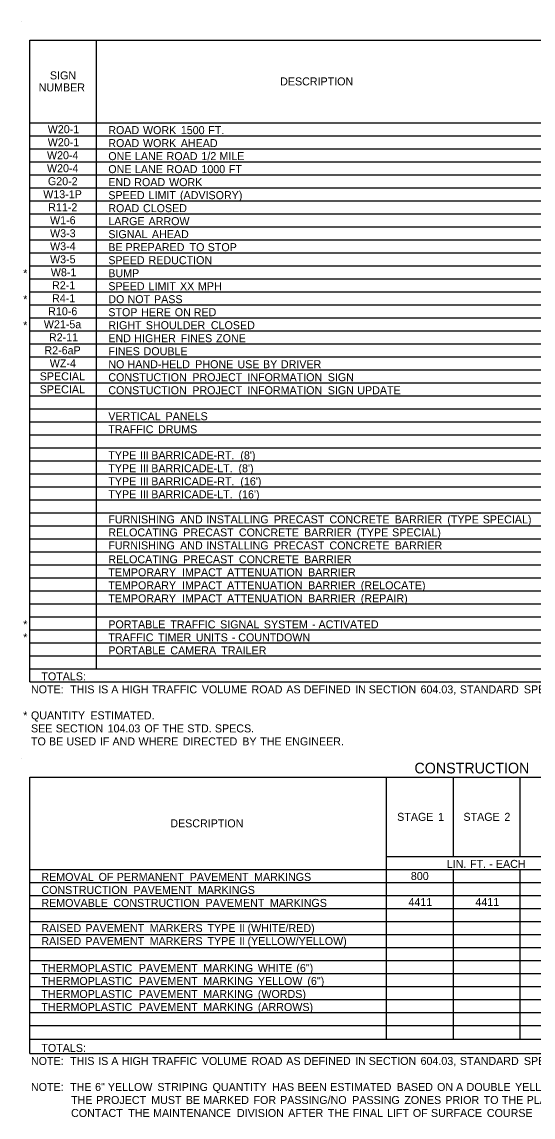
# Model space of a CAD drawing. Extents: x 107 to 7866, y 32 to 1473.
# Drawn here: x 107 to 490, y 67 to 888 of the extents above; entities that cross this region are included whole.
import ezdxf

# ---------------------------------------------------------------- set-up
doc = ezdxf.new("R2010")
doc.units = 0
doc.layers.add('Default', color=7, linetype='Continuous')

msp = doc.modelspace()

# ---------------------------------------------------------------- linework, layer by layer
at = {"layer": 'Default'}
for p, q in [((106.96, 888.35), (106.96, 888.35)), ((112.81, 874.7), (1625.52, 874.7)), ((112.81, 393.54), (112.81, 874.7)), ((112.81, 393.54), (112.81, 874.7)), ((163.02, 403.29), (163.02, 874.7)), ((112.81, 812.79), (1625.52, 812.79)), ((163.02, 500.79), (163.02, 812.79)), ((112.81, 803.04), (1625.52, 803.04)), ((112.81, 793.29), (1625.52, 793.29)), ((112.81, 783.54), (1625.52, 783.54)), ((112.81, 773.79), (1625.52, 773.79)), ((112.81, 764.04), (1625.52, 764.04)), ((112.81, 754.29), (1625.52, 754.29)), ((112.81, 744.54), (1625.52, 744.54)), ((112.81, 734.79), (1625.52, 734.79)), ((112.81, 725.04), (1625.52, 725.04)), ((112.81, 715.29), (1625.52, 715.29)), ((112.81, 705.54), (1625.52, 705.54)), ((112.81, 695.79), (1625.52, 695.79)), ((112.81, 686.04), (1625.52, 686.04)), ((112.81, 676.29), (1625.52, 676.29)), ((112.81, 666.54), (1625.52, 666.54)), ((112.81, 656.79), (1625.52, 656.79)), ((112.81, 647.04), (1625.52, 647.04)), ((112.81, 637.29), (1625.52, 637.29)), ((112.81, 627.54), (1625.52, 627.54)), ((112.81, 617.79), (1625.52, 617.79)), ((112.81, 608.04), (1625.52, 608.04)), ((112.81, 598.29), (1625.52, 598.29)), ((112.81, 588.54), (1625.52, 588.54)), ((112.81, 578.79), (1625.52, 578.79)), ((112.81, 569.04), (1625.52, 569.04)), ((112.81, 559.29), (1625.52, 559.29)), ((112.81, 549.54), (1625.52, 549.54)), ((112.81, 539.79), (1625.52, 539.79)), ((112.81, 530.04), (1625.52, 530.04)), ((112.81, 520.29), (1625.52, 520.29)), ((112.81, 510.54), (1625.52, 510.54)), ((112.81, 500.79), (163.02, 500.79)), ((112.81, 500.79), (1625.52, 500.79)), ((112.81, 491.04), (163.02, 491.04)), ((112.81, 491.04), (1625.52, 491.04)), ((163.02, 422.79), (163.02, 491.04)), ((112.81, 481.29), (1625.52, 481.29)), ((112.81, 471.54), (1625.52, 471.54)), ((112.81, 461.79), (1625.52, 461.79)), ((112.81, 452.04), (1625.52, 452.04)), ((112.81, 442.29), (1625.52, 442.29)), ((112.81, 432.54), (1625.52, 432.54)), ((112.81, 422.79), (1625.52, 422.79)), ((112.81, 413.04), (1625.52, 413.04)), ((163.02, 413.04), (495.01, 413.04)), ((163.02, 403.29), (163.02, 413.04)), ((112.81, 403.29), (1625.52, 403.29)), ((112.81, 393.54), (1625.52, 393.54)), ((106.96, 335.83), (106.96, 335.83)), ((112.81, 322.18), (1136.56, 322.18)), ((112.81, 114.99), (112.81, 322.18)), ((112.81, 114.99), (112.81, 322.18)), ((380.45, 125.71), (380.45, 322.18)), ((430.66, 262.7), (430.66, 322.18)), ((480.87, 262.7), (480.87, 322.18)), ((380.45, 262.7), (1136.56, 262.7)), ((112.81, 252.95), (1136.56, 252.95)), ((380.45, 125.71), (380.45, 252.95)), ((430.66, 125.71), (430.66, 252.95)), ((430.66, 125.71), (430.66, 252.95)), ((480.87, 125.71), (480.87, 252.95)), ((480.87, 125.71), (480.87, 252.95)), ((112.81, 243.2), (1136.56, 243.2)), ((112.81, 233.45), (1136.56, 233.45)), ((112.81, 223.7), (1136.56, 223.7)), ((112.81, 213.95), (1136.56, 213.95)), ((112.81, 204.2), (1136.56, 204.2)), ((112.81, 194.45), (1136.56, 194.45)), ((112.81, 184.7), (1136.56, 184.7)), ((112.81, 174.95), (1136.56, 174.95)), ((112.81, 165.2), (1136.56, 165.2)), ((112.81, 155.45), (1136.56, 155.45)), ((112.81, 145.7), (1136.56, 145.7)), ((112.81, 135.95), (1136.56, 135.95)), ((112.81, 125.71), (1136.56, 125.71)), ((112.81, 114.99), (1136.56, 114.99))]:
    msp.add_line(p, q, dxfattribs=at)

# ---------------------------------------------------------------- texts
for s, height, p in [('SIGN', 6, (128, 845.25)), ('DESCRIPTION', 6, (300.7, 840.75)), ('NUMBER', 6, (119.54, 836.25)), ('W20-1', 6, (126.34, 804.92)), ('ROAD', 6, (171.8, 804.24)), (' WORK', 6, (195.57, 804.24)), (' 1500', 6, (223.96, 804.24)), (' FT.', 6, (244.53, 804.24)), ('W20-1', 6, (126.34, 795.17)), ('ROAD', 6, (171.8, 794.49)), (' WORK', 6, (195.57, 794.49)), (' AHEAD', 6, (223.96, 794.49)), ('W20-4', 6, (125.78, 785.42)), ('ONE', 6, (171.8, 784.74)), (' LANE', 6, (189.52, 784.74)), (' ROAD', 6, (213.3, 784.74)), (' 1/2', 6, (239.4, 784.74)), (' MILE', 6, (252.93, 784.74)), ('W20-4', 6, (125.78, 775.67)), ('ONE', 6, (171.8, 774.99)), (' LANE', 6, (189.52, 774.99)), (' ROAD', 6, (213.3, 774.99)), (' 1000', 6, (239.4, 774.99)), (' FT', 6, (259.97, 774.99)), ('G20-2', 6, (126.49, 765.92)), ('END', 6, (171.8, 765.24)), (' ROAD', 6, (189.05, 765.24)), (' WORK', 6, (215.15, 765.24)), ('W13-1P', 6, (122.96, 756.17)), ('SPEED', 6, (171.8, 755.49)), (' LIMIT', 6, (199.77, 755.49)), (' (ADVISORY)', 6, (223.35, 755.49)), ('R11-2', 6, (126.72, 746.42)), ('ROAD', 6, (171.8, 745.74)), (' CLOSED', 6, (195.57, 745.74)), ('W1-6', 6, (128.09, 736.67)), ('LARGE', 6, (171.8, 735.99)), (' ARROW', 6, (199.77, 735.99)), ('W3-3', 6, (128.09, 726.92)), ('SIGNAL', 6, (171.8, 726.24)), (' AHEAD', 6, (202.25, 726.24)), ('W3-4', 6, (128.11, 717.17)), ('BE', 6, (171.8, 716.49)), (' PREPARED', 6, (182.53, 716.49)), (' TO', 6, (230.54, 716.49)), (' STOP', 6, (244.14, 716.49)), ('W3-5', 6, (128.07, 707.42)), ('SPEED', 6, (171.8, 706.74)), (' REDUCTION', 6, (199.77, 706.74)), ('*', 6, (107.93, 696.99)), ('W8-1', 6, (128.67, 697.67)), ('BUMP', 6, (171.8, 696.99)), ('R2-1', 6, (129.6, 687.92)), ('SPEED', 6, (171.8, 687.24)), (' LIMIT', 6, (199.77, 687.24)), (' XX', 6, (223.35, 687.24)), (' MPH', 6, (236.81, 687.24)), ('*', 6, (107.93, 677.49)), ('R4-1', 6, (129.6, 678.17)), ('DO', 6, (171.8, 677.49)), (' NOT', 6, (184, 677.49)), (' PASS', 6, (203.85, 677.49)), ('R10-6', 6, (126.69, 668.42)), ('STOP', 6, (171.8, 667.74)), (' HERE', 6, (194.26, 667.74)), (' ON', 6, (219.43, 667.74)), (' RED', 6, (233.65, 667.74)), ('*', 6, (107.93, 657.99)), ('W21-5a', 6, (123.42, 658.67)), ('RIGHT', 6, (171.8, 657.99)), (' SHOULDER', 6, (197.71, 657.99)), (' CLOSED', 6, (246.51, 657.99)), ('R2-11', 6, (127.27, 648.92)), ('END', 6, (171.8, 648.24)), (' HIGHER', 6, (189.05, 648.24)), (' FINES', 6, (223.87, 648.24)), (' ZONE', 6, (250.45, 648.24)), ('R2-6aP', 6, (123.89, 639.17)), ('FINES', 6, (171.8, 638.49)), (' DOUBLE', 6, (196.05, 638.49)), ('WZ-4', 6, (127.88, 629.42)), ('NO', 6, (171.8, 628.74)), (' HAND-HELD', 6, (184, 628.74)), (' PHONE', 6, (234.79, 628.74)), (' USE', 6, (266.48, 628.74)), (' BY', 6, (285.6, 628.74)), (' DRIVER', 6, (299.05, 628.74)), ('SPECIAL', 6, (120.36, 619.67)), ('CONSTUCTION', 6, (171.8, 618.99)), (' PROJECT', 6, (232.59, 618.99)), (' INFORMATION', 6, (273.88, 618.99)), (' SIGN', 6, (334.21, 618.99)), ('SPECIAL', 6, (120.36, 609.92)), ('CONSTUCTION', 6, (171.8, 609.24)), (' PROJECT', 6, (232.59, 609.24)), (' INFORMATION', 6, (273.88, 609.24)), (' SIGN', 6, (334.21, 609.24)), (' UPDATE', 6, (356.35, 609.24)), ('VERTICAL', 6, (171.8, 589.74)), (' PANELS', 6, (212.5, 589.74)), ('TRAFFIC', 6, (171.8, 579.99)), (' DRUMS', 6, (206.86, 579.99)), ('TYPE', 6, (171.8, 560.49)), (' III', 6, (193.25, 560.49)), (' BARRICADE-RT.', 6, (201.81, 560.49)), (" (8')", 6, (268.62, 560.49)), ('TYPE', 6, (171.8, 550.74)), (' III', 6, (193.25, 550.74)), (' BARRICADE-LT.', 6, (201.81, 550.74)), (" (8')", 6, (267.22, 550.74)), ('TYPE', 6, (171.8, 540.99)), (' III', 6, (193.25, 540.99)), (' BARRICADE-RT.', 6, (201.81, 540.99)), (" (16')", 6, (268.62, 540.99)), ('TYPE', 6, (171.8, 531.24)), (' III', 6, (193.25, 531.24)), (' BARRICADE-LT.', 6, (201.81, 531.24)), (" (16')", 6, (267.22, 531.24)), ('FURNISHING', 6, (171.8, 512.42)), (' AND', 6, (223.44, 512.42)), (' INSTALLING', 6, (243.02, 512.42)), (' PRECAST', 6, (293.73, 512.42)), (' CONCRETE', 6, (335.5, 512.42)), (' BARRIER', 6, (384.43, 512.42)), (' (TYPE', 6, (423.91, 512.42)), (' SPECIAL)', 6, (450.48, 512.42)), ('RELOCATING', 6, (171.8, 502.67)), (' PRECAST', 6, (225.77, 502.67)), (' CONCRETE', 6, (267.53, 502.67)), (' BARRIER', 6, (316.46, 502.67)), (' (TYPE', 6, (355.95, 502.67)), (' SPECIAL)', 6, (382.52, 502.67)), ('FURNISHING', 6, (171.8, 492.92)), (' AND', 6, (223.44, 492.92)), (' INSTALLING', 6, (243.02, 492.92)), (' PRECAST', 6, (293.73, 492.92)), (' CONCRETE', 6, (335.5, 492.92)), (' BARRIER', 6, (384.43, 492.92)), ('RELOCATING', 6, (171.8, 482.49)), (' PRECAST', 6, (225.77, 482.49)), (' CONCRETE', 6, (267.53, 482.49)), (' BARRIER', 6, (316.46, 482.49)), ('TEMPORARY', 6, (171.8, 472.74)), (' IMPACT', 6, (224.84, 472.74)), (' ATTENUATION', 6, (258.67, 472.74)), (' BARRIER', 6, (319.47, 472.74)), ('TEMPORARY', 6, (171.8, 462.99)), (' IMPACT', 6, (224.84, 462.99)), (' ATTENUATION', 6, (258.67, 462.99)), (' BARRIER', 6, (319.47, 462.99)), (' (RELOCATE)', 6, (358.96, 462.99)), ('TEMPORARY', 6, (171.8, 453.24)), (' IMPACT', 6, (224.84, 453.24)), (' ATTENUATION', 6, (258.67, 453.24)), (' BARRIER', 6, (319.47, 453.24)), (' (REPAIR)', 6, (358.96, 453.24)), ('*', 6, (107.93, 433.74)), ('PORTABLE', 6, (171.8, 433.74)), (' TRAFFIC', 6, (216.08, 433.74)), (' SIGNAL', 6, (253.47, 433.74)), (' SYSTEM', 6, (286.25, 433.74)), (' -', 6, (322.42, 433.74)), (' ACTIVATED', 6, (327.28, 433.74)), ('*', 6, (107.93, 423.99)), ('TRAFFIC', 6, (171.8, 423.99)), (' TIMER', 6, (206.86, 423.99)), (' UNITS', 6, (235.15, 423.99)), (' COUNTDOWN', 6, (267.05, 423.99)), ('PORTABLE', 6, (171.8, 414.24)), (' CAMERA', 6, (216.08, 414.24)), (' TRAILER', 6, (254.29, 414.24)), (' -', 6, (262.19, 423.99)), ('TOTALS:', 6, (121.58, 394.74)), ('NOTE:', 6, (113.78, 384.99)), ('  THIS', 6, (138.67, 384.99)), (' IS', 6, (161.98, 384.99)), (' A', 6, (171.79, 384.99)), (' HIGH', 6, (179.73, 384.99)), (' TRAFFIC', 6, (202.34, 384.99)), (' VOLUME', 6, (239.73, 384.99)), (' ROAD', 6, (277.01, 384.99)), (' AS', 6, (303.12, 384.99)), (' DEFINED', 6, (316.19, 384.99)), (' IN', 6, (354.87, 384.99)), (' SECTION', 6, (364.9, 384.99)), (' 604.03,', 6, (403.8, 384.99)), (' STANDARD', 6, (433.34, 384.99)), (' SPECIFICATIONS', 6, (481.34, 384.99)), ('*', 6, (107.93, 365.49)), ('QUANTITY', 6, (113.78, 365.49)), (' ESTIMATED.', 6, (156.11, 365.49)), ('SEE', 6, (113.78, 355.74)), (' SECTION', 6, (130.11, 355.74)), (' 104.03', 6, (169.02, 355.74)), (' OF', 6, (196.6, 355.74)), (' THE', 6, (210.19, 355.74)), (' STD.', 6, (228.83, 355.74)), (' SPECS.', 6, (249.53, 355.74)), ('TO', 6, (113.78, 345.99)), (' BE', 6, (125.05, 345.99)), (' USED', 6, (138.12, 345.99)), (' IF', 6, (163.29, 345.99)), (' AND', 6, (172.69, 345.99)), (' WHERE', 6, (192.27, 345.99)), (' DIRECTED', 6, (225.35, 345.99)), (' BY', 6, (270.09, 345.99)), (' THE', 6, (283.54, 345.99)), (' ENGINEER.', 6, (302.19, 345.99)), ('CONSTRUCTION', 8, (401.48, 325)), ('DESCRIPTION', 6, (218.31, 284.56)), ('STAGE', 6, (388.5, 289.44)), (' 1', 6, (416.97, 289.44)), ('STAGE', 6, (438.25, 289.44)), (' 2', 6, (466.71, 289.44)), ('LIN.', 6, (425.73, 254.15)), (' FT.', 6, (440.98, 254.15)), (' -', 6, (455.3, 254.15)), (' EACH', 6, (460.36, 254.15)), ('REMOVAL', 6, (121.58, 244.4)), (' OF', 6, (162.28, 244.4)), (' PERMANENT', 6, (175.87, 244.4)), (' PAVEMENT', 6, (230.67, 244.4)), (' MARKINGS', 6, (278.95, 244.4)), ('800', 6, (398.76, 245.08)), ('CONSTRUCTION', 6, (121.58, 234.65)), (' PAVEMENT', 6, (188.43, 234.65)), (' MARKINGS', 6, (236.72, 234.65)), ('REMOVABLE', 6, (121.58, 224.9)), (' CONSTRUCTION', 6, (173.32, 224.9)), (' PAVEMENT', 6, (242.5, 224.9)), (' MARKINGS', 6, (290.78, 224.9)), ('4411', 6, (397, 225.58)), ('4411', 6, (447.21, 225.58)), ('RAISED', 6, (121.58, 206.08)), (' PAVEMENT', 6, (152.35, 206.08)), (' MARKERS', 6, (200.63, 206.08)), (' TYPE', 6, (243.99, 206.08)), (' II', 6, (267.77, 206.08)), (' (WHITE/RED)', 6, (274, 206.08)), ('RAISED', 6, (121.58, 196.33)), (' PAVEMENT', 6, (152.35, 196.33)), (' MARKERS', 6, (200.63, 196.33)), (' TYPE', 6, (243.99, 196.33)), (' II', 6, (267.77, 196.33)), (' (YELLOW/YELLOW)', 6, (274, 196.33)), ('THERMOPLASTIC', 6, (121.58, 176.15)), (' PAVEMENT', 6, (192.52, 176.15)), (' MARKING', 6, (240.81, 176.15)), (' WHITE', 6, (281.74, 176.15)), (' (6")', 6, (310.62, 176.15)), ('THERMOPLASTIC', 6, (121.58, 166.4)), (' MARKING', 6, (240.81, 166.4)), (' YELLOW', 6, (281.74, 166.4)), (' (6")', 6, (318.91, 166.4)), (' PAVEMENT', 6, (192.52, 166.4)), ('THERMOPLASTIC', 6, (121.58, 156.65)), (' PAVEMENT', 6, (192.52, 156.65)), (' MARKING', 6, (240.81, 156.65)), (' (WORDS)', 6, (281.74, 156.65)), ('THERMOPLASTIC', 6, (121.58, 146.9)), (' PAVEMENT', 6, (192.52, 146.9)), (' MARKING', 6, (240.81, 146.9)), (' (ARROWS)', 6, (281.74, 146.9)), ('TOTALS:', 6, (121.58, 116.19)), ('NOTE:', 6, (113.78, 106.44)), ('  THIS', 6, (138.67, 106.44)), (' IS', 6, (161.98, 106.44)), (' A', 6, (171.79, 106.44)), (' HIGH', 6, (179.73, 106.44)), (' TRAFFIC', 6, (202.34, 106.44)), (' VOLUME', 6, (239.73, 106.44)), (' ROAD', 6, (277.01, 106.44)), (' AS', 6, (303.12, 106.44)), (' DEFINED', 6, (316.19, 106.44)), (' IN', 6, (354.87, 106.44)), (' SECTION', 6, (364.9, 106.44)), (' 604.03,', 6, (403.8, 106.44)), (' STANDARD', 6, (433.34, 106.44)), (' SPECIFICATIONS', 6, (481.34, 106.44)), ('NOTE:', 6, (113.78, 86.94)), ('  THE', 6, (138.67, 86.94)), (' 6"', 6, (159.65, 86.94)), (' YELLOW', 6, (169.22, 86.94)), (' STRIPING', 6, (206.39, 86.94)), (' QUANTITY', 6, (247.79, 86.94)), (' HAS', 6, (292.44, 86.94)), (' BEEN', 6, (311.57, 86.94)), (' ESTIMATED', 6, (336.04, 86.94)), (' BASED', 6, (385.9, 86.94)), (' ON', 6, (416.21, 86.94)), (' A', 6, (430.43, 86.94)), (' DOUBLE', 6, (438.36, 86.94)), (' YELLOW', 6, (474.72, 86.94)), ('   THE', 6, (137.18, 77.19)), (' PROJECT', 6, (160.49, 77.19)), (' MUST', 6, (201.78, 77.19)), (' BE', 6, (227.69, 77.19)), (' MARKED', 6, (240.76, 77.19)), (' FOR', 6, (278.51, 77.19)), (' PASSING/NO', 6, (298.42, 77.19)), (' PASSING', 6, (352.55, 77.19)), (' ZONES', 6, (391.63, 77.19)), (' PRIOR', 6, (422.4, 77.19)), (' TO', 6, (451.17, 77.19)), (' THE', 6, (464.76, 77.19)), (' PLACEMENT', 6, (483.41, 77.19)), ('   CONTACT', 6, (137.18, 67.44)), (' THE', 6, (184.52, 67.44)), (' MAINTENANCE', 6, (203.17, 67.44)), (' DIVISION', 6, (266.07, 67.44)), (' AFTER', 6, (304.52, 67.44)), (' THE', 6, (334.21, 67.44)), (' FINAL', 6, (352.86, 67.44)), (' LIFT', 6, (378.65, 67.44)), (' OF', 6, (398.04, 67.44)), (' SURFACE', 6, (411.63, 67.44)), (' COURSE', 6, (453.57, 67.44))]:
    msp.add_text(s, height=height, dxfattribs=at).set_placement(p)

doc.saveas('drawing.dxf')
